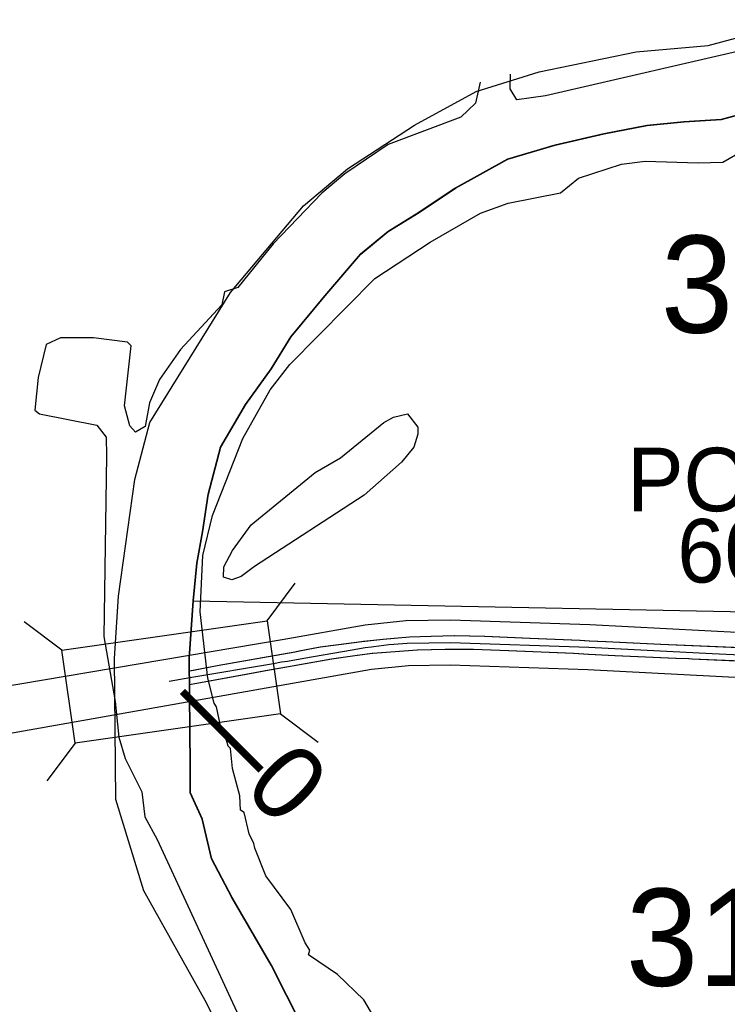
# Model space of a CAD drawing. Extents: x -132.8 to -73.3, y -60 to -26.
# Drawn here: x -127.907 to -126.96, y -43.738 to -42.42 of the extents above; entities that cross this region are included whole.
import ezdxf

# ---------------------------------------------------------------- set-up
doc = ezdxf.new("R2010")
doc.units = 0
for name, color, linetype in [('tdCoClipBndry', 7, 'Continuous'), ('tdCoCoBndry', 7, 'Continuous'), ('tdCoDivCarto', 7, 'Continuous'), ('tdCoHydroRiver', 7, 'Continuous'), ('tdCoInt', 7, 'Continuous'), ('tdCoIntCL', 7, 'Continuous'), ('tdCoIntRte', 7, 'Continuous'), ('tdCoPrimary', 7, 'Continuous'), ('tdCoSectLine', 7, 'Continuous'), ('tdCoSectLinePart', 7, 'Continuous'), ('tdCoSectNmbr', 7, 'Continuous'), ('tdCoStBndry', 7, 'Continuous'), ('tdCoStBndryPart', 7, 'Continuous'), ('tdCoStrucNonDivPri', 7, 'Continuous'), ('tdCoStrucSecCoName', 7, 'Continuous'), ('tdCoStrucSecFHWANum', 7, 'Continuous'), ('tdCoTwpBndryShd', 7, 'Continuous'), ('tdStHwyIntRefPost5', 7, 'Continuous')]:
    doc.layers.add(name, color=color, linetype=linetype)

msp = doc.modelspace()

# ---------------------------------------------------------------- linework, layer by layer
at = {"layer": 'tdCoClipBndry'}
msp.add_lwpolyline([(-126.7711, -44.7076), (-127.1421, -44.4077), (-127.2956, -44.2611), (-127.4947, -44.0324), (-127.5405, -43.962), (-127.6585, -43.7323), (-127.7404, -43.5856), (-127.7781, -43.4634), (-127.7798, -43.2751), (-127.7746, -43.1914), (-127.7526, -43.0354), (-127.7325, -42.9593), (-127.6247, -42.7855), (-127.527, -42.6696), (-127.4684, -42.6199), (-127.3787, -42.5617), (-127.2961, -42.5163), (-127.2117, -42.4902), (-127.0823, -42.4632), (-126.986, -42.455), (-126.8582, -42.4204)], dxfattribs=at)
at = {"layer": 'tdCoCoBndry'}
for p, q in [((-126.9683, -42.5539), (-126.8843, -42.5311)), ((-127.0182, -42.557), (-126.9683, -42.5539)), ((-127.125, -42.5729), (-127.0675, -42.5621)), ((-127.0675, -42.5621), (-127.0182, -42.557)), ((-127.1907, -42.5881), (-127.125, -42.5729)), ((-127.2539, -42.607), (-127.1907, -42.5881)), ((-127.324, -42.6456), (-127.2539, -42.607)), ((-127.3726, -42.6785), (-127.324, -42.6456)), ((-127.4137, -42.7038), (-127.3726, -42.6785)), ((-127.4503, -42.7341), (-127.4137, -42.7038)), ((-127.4983, -42.7897), (-127.4503, -42.7341)), ((-127.5438, -42.8447), (-127.4983, -42.7897)), ((-127.57, -42.8875), (-127.5438, -42.8447)), ((-127.6044, -42.9351), (-127.57, -42.8875)), ((-127.6377, -42.9922), (-127.6044, -42.9351)), ((-127.6543, -43.0551), (-127.6377, -42.9922)), ((-127.6618, -43.1057), (-127.6543, -43.0551)), ((-127.6694, -43.1474), (-127.6618, -43.1057)), ((-127.6744, -43.1979), (-127.6694, -43.1474)), ((-127.6795, -43.2744), (-127.6744, -43.1979)), ((-127.6781, -43.4184), (-127.6795, -43.2744)), ((-127.6781, -43.4545), (-127.6781, -43.4184)), ((-127.6623, -43.4898), (-127.6781, -43.4545)), ((-127.6497, -43.5429), (-127.6623, -43.4898)), ((-127.6225, -43.5947), (-127.6497, -43.5429)), ((-127.57, -43.685), (-127.6225, -43.5947)), ((-127.4884, -43.8467), (-127.57, -43.685))]:
    msp.add_line(p, q, dxfattribs=at)
for points in [[(-126.8846, -42.5311), (-126.9687, -42.5539), (-127.0186, -42.557), (-127.0679, -42.5621), (-127.1254, -42.5729), (-127.1911, -42.5881), (-127.2542, -42.607), (-127.3243, -42.6456), (-127.373, -42.6785), (-127.414, -42.7038), (-127.4507, -42.7341), (-127.4987, -42.7897), (-127.5441, -42.8447), (-127.5704, -42.8875), (-127.6048, -42.9351), (-127.638, -42.9922), (-127.6546, -43.0551), (-127.6622, -43.1057), (-127.6698, -43.1474), (-127.6748, -43.1979), (-127.6798, -43.2744), (-127.6785, -43.4184), (-127.6785, -43.4545), (-127.6627, -43.4898), (-127.65, -43.5429), (-127.6229, -43.5947), (-127.5704, -43.685), (-127.4888, -43.8467)], [(-127.4884, -43.8467), (-127.57, -43.685), (-127.6225, -43.5947), (-127.6497, -43.5429), (-127.6623, -43.4898), (-127.6781, -43.4545), (-127.6781, -43.4184), (-127.6795, -43.2744), (-127.6744, -43.1979), (-127.6694, -43.1474), (-127.6618, -43.1057), (-127.6543, -43.0551), (-127.6377, -42.9922), (-127.6044, -42.9351), (-127.57, -42.8875), (-127.5438, -42.8447), (-127.4983, -42.7897), (-127.4503, -42.7341), (-127.4137, -42.7038), (-127.3726, -42.6785), (-127.324, -42.6456), (-127.2539, -42.607), (-127.1907, -42.5881), (-127.125, -42.5729), (-127.0675, -42.5621), (-127.0182, -42.557), (-126.9683, -42.5539), (-126.8843, -42.5311)]]:
    msp.add_lwpolyline(points, dxfattribs=at)
at = {"layer": 'tdCoDivCarto'}
for p, q in [((-127.4492, -43.2525), (-127.4798, -43.2565)), ((-127.4467, -43.2522), (-127.4492, -43.2525)), ((-127.4206, -43.2493), (-127.4467, -43.2522)), ((-127.3851, -43.2466), (-127.4206, -43.2493)), ((-127.3562, -43.2456), (-127.3851, -43.2466)), ((-127.3247, -43.2446), (-127.3562, -43.2456)), ((-127.2845, -43.2456), (-127.3247, -43.2446)), ((-127.224, -43.2483), (-127.2845, -43.2456)), ((-127.1572, -43.251), (-127.224, -43.2483)), ((-127.1447, -43.2517), (-127.1572, -43.251)), ((-127.1224, -43.2528), (-127.1447, -43.2517)), ((-127.0492, -43.256), (-127.1224, -43.2528)), ((-127.5323, -43.2653), (-127.5382, -43.2664)), ((-127.5042, -43.2599), (-127.5323, -43.2653)), ((-127.4798, -43.2565), (-127.5042, -43.2599)), ((-127.4342, -43.268), (-127.3985, -43.2653)), ((-127.3985, -43.2653), (-127.3748, -43.2635)), ((-127.3748, -43.2635), (-127.3373, -43.2625)), ((-127.3373, -43.2625), (-127.2996, -43.2625)), ((-127.2996, -43.2625), (-127.2527, -43.2643)), ((-127.2527, -43.2643), (-127.1654, -43.268)), ((-126.85, -43.2648), (-127.0492, -43.256)), ((-127.5814, -43.274), (-127.6423, -43.2848)), ((-127.5382, -43.2664), (-127.5814, -43.274)), ((-127.5469, -43.2856), (-127.4892, -43.2754)), ((-127.4892, -43.2754), (-127.4582, -43.2707)), ((-127.4582, -43.2707), (-127.4348, -43.268)), ((-127.4348, -43.268), (-127.4342, -43.268)), ((-127.1654, -43.268), (-127.1456, -43.269)), ((-127.1456, -43.269), (-127.1104, -43.2709)), ((-127.1104, -43.2709), (-127.0288, -43.2744)), ((-127.0288, -43.2744), (-127.0118, -43.2751)), ((-127.0118, -43.2751), (-127.0075, -43.2753)), ((-127.0075, -43.2753), (-126.8676, -43.2814)), ((-127.0075, -43.2753), (-126.8676, -43.2814)), ((-127.6768, -43.2915), (-127.6794, -43.292)), ((-127.6768, -43.2915), (-127.6794, -43.292)), ((-127.6741, -43.291), (-127.6768, -43.2915)), ((-127.6423, -43.2848), (-127.6741, -43.291)), ((-127.6037, -43.2958), (-127.5726, -43.2902)), ((-127.5726, -43.2902), (-127.5595, -43.2879)), ((-127.5595, -43.2879), (-127.5469, -43.2856)), ((-127.6793, -43.3097), (-127.6037, -43.2958))]:
    msp.add_line(p, q, dxfattribs=at)
for points in [[(-127.4368, -43.2511), (-127.4492, -43.2525), (-127.4798, -43.2565), (-127.5042, -43.2599), (-127.5323, -43.2653), (-127.5382, -43.2664), (-127.5814, -43.274), (-127.6423, -43.2848), (-127.6741, -43.291), (-127.6768, -43.2915)], [(-127.4368, -43.2511), (-127.4492, -43.2525), (-127.4798, -43.2565), (-127.5042, -43.2599), (-127.5323, -43.2653), (-127.5382, -43.2664), (-127.5814, -43.274), (-127.6423, -43.2848), (-127.6741, -43.291), (-127.6768, -43.2915)], [(-127.4467, -43.2522), (-127.4492, -43.2525), (-127.4798, -43.2565), (-127.5042, -43.2599), (-127.5323, -43.2653), (-127.5382, -43.2664), (-127.5814, -43.274), (-127.6423, -43.2848), (-127.6741, -43.291), (-127.6768, -43.2915)], [(-127.1447, -43.2517), (-127.1572, -43.251), (-127.224, -43.2483), (-127.2845, -43.2456), (-127.3247, -43.2446), (-127.3562, -43.2456), (-127.3851, -43.2466), (-127.4206, -43.2493), (-127.4467, -43.2522)], [(-127.1447, -43.2517), (-127.1572, -43.251), (-127.224, -43.2483), (-127.2845, -43.2456), (-127.3247, -43.2446), (-127.3562, -43.2456), (-127.3851, -43.2466), (-127.4206, -43.2493), (-127.4368, -43.2511)], [(-127.1447, -43.2517), (-127.1572, -43.251), (-127.224, -43.2483), (-127.2845, -43.2456), (-127.3247, -43.2446), (-127.3562, -43.2456), (-127.3851, -43.2466), (-127.4206, -43.2493), (-127.4368, -43.2511)], [(-126.85, -43.2648), (-127.0492, -43.256), (-127.1224, -43.2528), (-127.1447, -43.2517)], [(-126.85, -43.2648), (-127.0492, -43.256), (-127.1224, -43.2528), (-127.1447, -43.2517)], [(-126.85, -43.2648), (-127.0492, -43.256), (-127.1224, -43.2528), (-127.1447, -43.2517)], [(-127.4348, -43.268), (-127.4342, -43.268), (-127.3985, -43.2653), (-127.3748, -43.2635), (-127.3373, -43.2625), (-127.2996, -43.2625), (-127.2527, -43.2643), (-127.1654, -43.268), (-127.1456, -43.269)], [(-127.4348, -43.268), (-127.4342, -43.268), (-127.3985, -43.2653), (-127.3748, -43.2635), (-127.3373, -43.2625), (-127.2996, -43.2625), (-127.2527, -43.2643), (-127.1654, -43.268), (-127.1456, -43.269)], [(-127.4348, -43.268), (-127.4342, -43.268), (-127.3985, -43.2653), (-127.3748, -43.2635), (-127.3373, -43.2625), (-127.2996, -43.2625), (-127.2527, -43.2643), (-127.1654, -43.268), (-127.1456, -43.269)], [(-127.5469, -43.2856), (-127.4892, -43.2754), (-127.4582, -43.2707), (-127.4348, -43.268)], [(-127.5469, -43.2856), (-127.4892, -43.2754), (-127.4582, -43.2707), (-127.4348, -43.268)], [(-127.5469, -43.2856), (-127.4892, -43.2754), (-127.4582, -43.2707), (-127.4348, -43.268)], [(-127.1456, -43.269), (-127.1104, -43.2709), (-127.0288, -43.2744), (-127.0118, -43.2751), (-127.0075, -43.2753)], [(-127.1456, -43.269), (-127.1104, -43.2709), (-127.0288, -43.2744), (-127.0118, -43.2751), (-127.0075, -43.2753)], [(-127.1456, -43.269), (-127.1104, -43.2709), (-127.0288, -43.2744), (-127.0118, -43.2751), (-127.0075, -43.2753)], [(-127.0075, -43.2753), (-126.8676, -43.2814)], [(-127.0075, -43.2753), (-126.8676, -43.2814)], [(-127.6768, -43.2915), (-127.6794, -43.292)], [(-127.6768, -43.2915), (-127.6794, -43.292)], [(-127.6793, -43.3097), (-127.6037, -43.2958), (-127.5726, -43.2902), (-127.5595, -43.2879), (-127.5469, -43.2856)], [(-127.6793, -43.3097), (-127.6037, -43.2958), (-127.5726, -43.2902), (-127.5595, -43.2879), (-127.5469, -43.2856)], [(-127.6793, -43.3097), (-127.6037, -43.2958), (-127.5726, -43.2902), (-127.5595, -43.2879), (-127.5469, -43.2856)]]:
    msp.add_lwpolyline(points, dxfattribs=at)
at = {"layer": 'tdCoHydroRiver'}
for points in [[(-126.9176, -42.4563), (-127.2036, -42.5223), (-127.2416, -42.5275), (-127.2507, -42.513), (-127.2501, -42.4933)], [(-127.2908, -42.5041), (-127.297, -42.5322), (-127.3165, -42.5506), (-127.4138, -42.5872), (-127.4717, -42.6266), (-127.5025, -42.6526), (-127.5675, -42.7201), (-127.615, -42.7787), (-127.6325, -42.7845), (-127.6361, -42.8018), (-127.6915, -42.8617), (-127.7195, -42.9019), (-127.733, -42.9331), (-127.7386, -42.9645), (-127.7515, -42.972), (-127.7591, -42.9639), (-127.7663, -42.9369), (-127.7577, -42.8567), (-127.7623, -42.8518), (-127.8079, -42.8458), (-127.8521, -42.8461), (-127.8712, -42.855), (-127.882, -42.8989), (-127.8864, -42.9429), (-127.8802, -42.9478), (-127.8033, -42.9626), (-127.7911, -42.9788), (-127.7903, -43.004), (-127.794, -43.2453), (-127.7791, -43.3325), (-127.7741, -43.38), (-127.7655, -43.4086), (-127.7431, -43.4534), (-127.7393, -43.4867), (-127.7228, -43.5171), (-127.6083, -43.7649)], [(-127.4328, -43.7542), (-127.4464, -43.7317), (-127.4817, -43.6976), (-127.5204, -43.6712), (-127.5187, -43.6649), (-127.5247, -43.6553), (-127.5439, -43.6106), (-127.5774, -43.5655), (-127.5921, -43.5287), (-127.5935, -43.5224), (-127.5995, -43.5096), (-127.6066, -43.481), (-127.6112, -43.4777), (-127.6122, -43.4588), (-127.6222, -43.4222), (-127.6246, -43.3953), (-127.6277, -43.3921), (-127.6291, -43.3873), (-127.6335, -43.3745), (-127.6349, -43.3682), (-127.638, -43.3649), (-127.6436, -43.3395), (-127.6466, -43.3347), (-127.6551, -43.3013), (-127.6652, -43.2127), (-127.6615, -43.1371), (-127.6489, -43.0838), (-127.6081, -42.9808), (-127.5715, -42.9156), (-127.5453, -42.8817), (-127.4315, -42.7666), (-127.3576, -42.7182), (-127.2902, -42.6791), (-127.2535, -42.666), (-127.1836, -42.6522), (-127.1594, -42.6324), (-127.102, -42.6135), (-127.0704, -42.6097), (-126.9994, -42.6117), (-126.9662, -42.6111), (-126.9325, -42.5915)], [(-127.6229, -43.1697), (-127.6339, -43.1663), (-127.6335, -43.1521), (-127.6218, -43.1303), (-127.5972, -43.0963), (-127.5115, -43.0262), (-127.4778, -43.0067), (-127.4197, -42.9594), (-127.4068, -42.9519), (-127.3878, -42.9477), (-127.3741, -42.9654), (-127.3743, -42.9749), (-127.3796, -42.9921), (-127.3959, -43.0122), (-127.4461, -43.0565), (-127.5924, -43.1517), (-127.6102, -43.1654), (-127.6229, -43.1697)]]:
    msp.add_lwpolyline(points, dxfattribs=at)
at = {"layer": 'tdCoInt'}
for points in [[(-127.9729, -43.32), (-127.5558, -43.2493), (-127.4444, -43.2298), (-127.3901, -43.2243), (-127.3303, -43.2234), (-127.1442, -43.2296), (-126.8877, -43.2429), (-126.6972, -43.2498), (-126.6539, -43.2516)], [(-127.9572, -43.3815), (-127.436, -43.2893), (-127.3868, -43.2843), (-127.3308, -43.2834), (-127.1468, -43.2895), (-126.8902, -43.3028), (-126.6988, -43.3098), (-126.6675, -43.3108)]]:
    msp.add_lwpolyline(points, dxfattribs=at)
at = {"layer": 'tdCoIntCL'}
msp.add_lwpolyline([(-127.7069, -43.3052), (-127.6789, -43.3005), (-127.5673, -43.2815), (-127.5565, -43.2796), (-127.5486, -43.2783), (-127.5264, -43.2746), (-127.4622, -43.2634), (-127.4445, -43.2604), (-127.4362, -43.2592), (-127.4332, -43.2587), (-127.4131, -43.2562), (-127.4064, -43.2557), (-127.3885, -43.2543), (-127.3596, -43.2539), (-127.3306, -43.2534), (-127.1455, -43.2596), (-126.9807, -43.2681), (-126.8859, -43.2729)], dxfattribs=at)
at = {"layer": 'tdCoIntRte'}
for points in [[(-126.8504, -43.2648), (-127.0496, -43.256), (-127.1228, -43.2528), (-127.1451, -43.2517), (-127.1576, -43.251), (-127.2244, -43.2483), (-127.2848, -43.2456), (-127.325, -43.2446), (-127.3566, -43.2456), (-127.3855, -43.2466), (-127.421, -43.2493), (-127.4371, -43.2511), (-127.4496, -43.2525), (-127.4802, -43.2565), (-127.5046, -43.2599), (-127.5327, -43.2653), (-127.5386, -43.2664), (-127.5818, -43.274), (-127.6427, -43.2848), (-127.6745, -43.291), (-127.6771, -43.2915), (-127.6798, -43.292)], [(-126.8504, -43.2648), (-127.0496, -43.256), (-127.1228, -43.2528), (-127.1451, -43.2517), (-127.1576, -43.251), (-127.2244, -43.2483), (-127.2848, -43.2456), (-127.325, -43.2446), (-127.3566, -43.2456), (-127.3855, -43.2466), (-127.421, -43.2493), (-127.4371, -43.2511), (-127.4496, -43.2525), (-127.4802, -43.2565), (-127.5046, -43.2599), (-127.5327, -43.2653), (-127.5386, -43.2664), (-127.5818, -43.274), (-127.6427, -43.2848), (-127.6745, -43.291), (-127.6771, -43.2915), (-127.6798, -43.292)], [(-127.6797, -43.3097), (-127.604, -43.2958), (-127.573, -43.2902), (-127.5599, -43.2879), (-127.5473, -43.2856), (-127.4896, -43.2754), (-127.4585, -43.2707), (-127.4352, -43.268), (-127.4346, -43.268), (-127.3989, -43.2653), (-127.3752, -43.2635), (-127.3377, -43.2625), (-127.3, -43.2625), (-127.2531, -43.2643), (-127.1658, -43.268), (-127.146, -43.269), (-127.1108, -43.2709), (-127.0292, -43.2744), (-127.0122, -43.2751), (-127.0079, -43.2753), (-126.868, -43.2814)], [(-127.6797, -43.3097), (-127.604, -43.2958), (-127.573, -43.2902), (-127.5599, -43.2879), (-127.5473, -43.2856), (-127.4896, -43.2754), (-127.4585, -43.2707), (-127.4352, -43.268), (-127.4346, -43.268), (-127.3989, -43.2653), (-127.3752, -43.2635), (-127.3377, -43.2625), (-127.3, -43.2625), (-127.2531, -43.2643), (-127.1658, -43.268), (-127.146, -43.269), (-127.1108, -43.2709), (-127.0292, -43.2744), (-127.0122, -43.2751), (-127.0079, -43.2753), (-126.868, -43.2814)]]:
    msp.add_lwpolyline(points, dxfattribs=at)
at = {"layer": 'tdCoPrimary'}
for p, q in [((-127.0075, -43.2753), (-126.8676, -43.2814)), ((-127.0075, -43.2753), (-126.8676, -43.2814)), ((-127.6768, -43.2915), (-127.6794, -43.292)), ((-127.6768, -43.2915), (-127.6794, -43.292))]:
    msp.add_line(p, q, dxfattribs=at)
for points in [[(-126.85, -43.2648), (-127.0492, -43.256), (-127.1224, -43.2528), (-127.1447, -43.2517), (-127.1572, -43.251), (-127.224, -43.2483), (-127.2845, -43.2456), (-127.3247, -43.2446), (-127.3562, -43.2456), (-127.3851, -43.2466), (-127.4206, -43.2493), (-127.4467, -43.2522), (-127.4492, -43.2525), (-127.4798, -43.2565), (-127.5042, -43.2599), (-127.5323, -43.2653), (-127.5382, -43.2664), (-127.5814, -43.274), (-127.6423, -43.2848), (-127.6741, -43.291), (-127.6768, -43.2915), (-127.6794, -43.292)], [(-127.4467, -43.2522), (-127.4492, -43.2525), (-127.4798, -43.2565), (-127.5042, -43.2599), (-127.5323, -43.2653), (-127.5382, -43.2664), (-127.5814, -43.274), (-127.6423, -43.2848), (-127.6741, -43.291), (-127.6768, -43.2915)], [(-127.4467, -43.2522), (-127.4492, -43.2525), (-127.4798, -43.2565), (-127.5042, -43.2599), (-127.5323, -43.2653), (-127.5382, -43.2664), (-127.5814, -43.274), (-127.6423, -43.2848), (-127.6741, -43.291), (-127.6768, -43.2915)], [(-127.1447, -43.2517), (-127.1572, -43.251), (-127.224, -43.2483), (-127.2845, -43.2456), (-127.3247, -43.2446), (-127.3562, -43.2456), (-127.3851, -43.2466), (-127.4206, -43.2493), (-127.4467, -43.2522)], [(-127.1447, -43.2517), (-127.1572, -43.251), (-127.224, -43.2483), (-127.2845, -43.2456), (-127.3247, -43.2446), (-127.3562, -43.2456), (-127.3851, -43.2466), (-127.4206, -43.2493), (-127.4467, -43.2522)], [(-126.85, -43.2648), (-127.0492, -43.256), (-127.1224, -43.2528), (-127.1447, -43.2517)], [(-126.85, -43.2648), (-127.0492, -43.256), (-127.1224, -43.2528), (-127.1447, -43.2517)], [(-127.6793, -43.3097), (-127.6037, -43.2958), (-127.5726, -43.2902), (-127.5595, -43.2879), (-127.5469, -43.2856), (-127.4892, -43.2754), (-127.4582, -43.2707), (-127.4348, -43.268), (-127.4342, -43.268), (-127.3985, -43.2653), (-127.3748, -43.2635), (-127.3373, -43.2625), (-127.2996, -43.2625), (-127.2527, -43.2643), (-127.1654, -43.268), (-127.1456, -43.269), (-127.1104, -43.2709), (-127.0288, -43.2744), (-127.0118, -43.2751), (-127.0075, -43.2753), (-126.8676, -43.2814)], [(-127.4348, -43.268), (-127.4342, -43.268), (-127.3985, -43.2653), (-127.3748, -43.2635), (-127.3373, -43.2625), (-127.2996, -43.2625), (-127.2527, -43.2643), (-127.1654, -43.268), (-127.1456, -43.269)], [(-127.4348, -43.268), (-127.4342, -43.268), (-127.3985, -43.2653), (-127.3748, -43.2635), (-127.3373, -43.2625), (-127.2996, -43.2625), (-127.2527, -43.2643), (-127.1654, -43.268), (-127.1456, -43.269)], [(-127.5469, -43.2856), (-127.4892, -43.2754), (-127.4582, -43.2707), (-127.4348, -43.268)], [(-127.5469, -43.2856), (-127.4892, -43.2754), (-127.4582, -43.2707), (-127.4348, -43.268)], [(-127.1456, -43.269), (-127.1104, -43.2709), (-127.0288, -43.2744), (-127.0118, -43.2751), (-127.0075, -43.2753)], [(-127.1456, -43.269), (-127.1104, -43.2709), (-127.0288, -43.2744), (-127.0118, -43.2751), (-127.0075, -43.2753)], [(-127.6793, -43.3097), (-127.6037, -43.2958), (-127.5726, -43.2902), (-127.5595, -43.2879), (-127.5469, -43.2856)], [(-127.6793, -43.3097), (-127.6037, -43.2958), (-127.5726, -43.2902), (-127.5595, -43.2879), (-127.5469, -43.2856)]]:
    msp.add_lwpolyline(points, dxfattribs=at)
at = {"layer": 'tdCoSectLine'}
for points in [[(-126.8846, -42.5311), (-126.9687, -42.5539), (-127.0186, -42.557), (-127.0679, -42.5621), (-127.1254, -42.5729), (-127.1911, -42.5881), (-127.2542, -42.607), (-127.3243, -42.6456), (-127.373, -42.6785), (-127.414, -42.7038), (-127.4507, -42.7341), (-127.4987, -42.7897), (-127.5441, -42.8447), (-127.5704, -42.8875), (-127.6048, -42.9351), (-127.638, -42.9922), (-127.6546, -43.0551), (-127.6622, -43.1057), (-127.6698, -43.1474), (-127.6748, -43.1979)], [(-127.6748, -43.1979), (-127.6798, -43.2744), (-127.6785, -43.4184), (-127.6785, -43.4545), (-127.6627, -43.4898), (-127.65, -43.5429), (-127.6229, -43.5947), (-127.5704, -43.685), (-127.4888, -43.8467), (-127.4559, -43.9087), (-127.4193, -43.9668), (-127.3493, -44.0471), (-127.3133, -44.0885), (-127.2627, -44.1466), (-127.2202, -44.1954)], [(-127.6748, -43.1979), (-126.6872, -43.2173)]]:
    msp.add_lwpolyline(points, dxfattribs=at)
at = {"layer": 'tdCoSectLinePart'}
for points in [[(-126.8846, -42.5311), (-126.9687, -42.5539), (-127.0186, -42.557), (-127.0679, -42.5621), (-127.1254, -42.5729), (-127.1911, -42.5881), (-127.2542, -42.607), (-127.3243, -42.6456), (-127.373, -42.6785), (-127.414, -42.7038), (-127.4507, -42.7341), (-127.4987, -42.7897), (-127.5441, -42.8447), (-127.5704, -42.8875), (-127.6048, -42.9351), (-127.638, -42.9922), (-127.6546, -43.0551), (-127.6622, -43.1057), (-127.6698, -43.1474), (-127.6748, -43.1979)], [(-127.6748, -43.1979), (-127.6798, -43.2744), (-127.6785, -43.4184), (-127.6785, -43.4545), (-127.6627, -43.4898), (-127.65, -43.5429), (-127.6229, -43.5947), (-127.5704, -43.685), (-127.4888, -43.8467), (-127.4559, -43.9087), (-127.4193, -43.9668), (-127.3493, -44.0471), (-127.3133, -44.0885), (-127.2627, -44.1466), (-127.2202, -44.1954)], [(-127.6748, -43.1979), (-126.6872, -43.2173)]]:
    msp.add_lwpolyline(points, dxfattribs=at)
at = {"layer": 'tdCoStBndry'}
msp.add_lwpolyline([(-126.8846, -42.5311), (-126.9687, -42.5539), (-127.0186, -42.557), (-127.0679, -42.5621), (-127.1254, -42.5729), (-127.1911, -42.5881), (-127.2542, -42.607), (-127.3243, -42.6456), (-127.373, -42.6785), (-127.414, -42.7038), (-127.4507, -42.7341), (-127.4987, -42.7897), (-127.5441, -42.8447), (-127.5704, -42.8875), (-127.6048, -42.9351), (-127.638, -42.9922), (-127.6546, -43.0551), (-127.6622, -43.1057), (-127.6698, -43.1474), (-127.6748, -43.1979), (-127.6798, -43.2744), (-127.6785, -43.4184), (-127.6785, -43.4545), (-127.6627, -43.4898), (-127.65, -43.5429), (-127.6229, -43.5947), (-127.5704, -43.685), (-127.4888, -43.8467)], dxfattribs=at)
at = {"layer": 'tdCoStBndryPart'}
msp.add_lwpolyline([(-126.8846, -42.5311), (-126.9687, -42.5539), (-127.0186, -42.557), (-127.0679, -42.5621), (-127.1254, -42.5729), (-127.1911, -42.5881), (-127.2542, -42.607), (-127.3243, -42.6456), (-127.373, -42.6785), (-127.414, -42.7038), (-127.4507, -42.7341), (-127.4987, -42.7897), (-127.5441, -42.8447), (-127.5704, -42.8875), (-127.6048, -42.9351), (-127.638, -42.9922), (-127.6546, -43.0551), (-127.6622, -43.1057), (-127.6698, -43.1474), (-127.6748, -43.1979), (-127.6798, -43.2744), (-127.6785, -43.4184), (-127.6785, -43.4545), (-127.6627, -43.4898), (-127.65, -43.5429), (-127.6229, -43.5947), (-127.5704, -43.685), (-127.4888, -43.8467)], dxfattribs=at)
at = {"layer": 'tdCoStrucNonDivPri'}
for p, q in [((-127.5758, -43.2244), (-127.538, -43.174)), ((-127.8502, -43.2636), (-127.9006, -43.2258)), ((-127.8502, -43.2636), (-127.5758, -43.2244)), ((-127.5758, -43.2244), (-127.558, -43.3491)), ((-127.8324, -43.3883), (-127.8502, -43.2636)), ((-127.558, -43.3491), (-127.8324, -43.3883)), ((-127.558, -43.3491), (-127.5076, -43.3869)), ((-127.8324, -43.3883), (-127.8701, -43.4387)), ((-127.8324, -43.3883), (-127.8324, -43.3883))]:
    msp.add_line(p, q, dxfattribs=at)
at = {"layer": 'tdCoTwpBndryShd'}
msp.add_lwpolyline([(-127.4888, -43.8467), (-127.5704, -43.685), (-127.6229, -43.5947), (-127.65, -43.5429), (-127.6627, -43.4898), (-127.6785, -43.4545), (-127.6785, -43.4184), (-127.6798, -43.2744), (-127.6748, -43.1979), (-127.6698, -43.1474), (-127.6622, -43.1057), (-127.6546, -43.0551), (-127.638, -42.9922), (-127.6048, -42.9351), (-127.5704, -42.8875), (-127.5441, -42.8447), (-127.4987, -42.7897), (-127.4507, -42.7341), (-127.414, -42.7038), (-127.373, -42.6785), (-127.3243, -42.6456), (-127.2542, -42.607), (-127.1911, -42.5881), (-127.1254, -42.5729), (-127.0679, -42.5621), (-127.0186, -42.557), (-126.9687, -42.5539), (-126.8846, -42.5311)], dxfattribs=at)

# ---------------------------------------------------------------- texts
at = {"layer": 'tdCoSectNmbr'}
for s, p in [('30', (-127.0493, -42.8391)), ('31', (-127.096, -43.7127))]:
    msp.add_text(s, height=0.13, rotation=359.9049, dxfattribs=at).set_placement(p)
at = {"layer": 'tdCoStrucSecCoName'}
msp.add_text('POTTAWATTAMIE', height=0.085, dxfattribs=at).set_placement((-127.0945, -43.078))
at = {"layer": 'tdCoStrucSecFHWANum'}
msp.add_text('603307', height=0.085, dxfattribs=at).set_placement((-127.0273, -43.1733))
at = {"layer": 'tdStHwyIntRefPost5'}
msp.add_text('‒‒0', height=0.1, rotation=315, dxfattribs=at).set_placement((-127.715, -43.3451))

doc.saveas('drawing.dxf')
